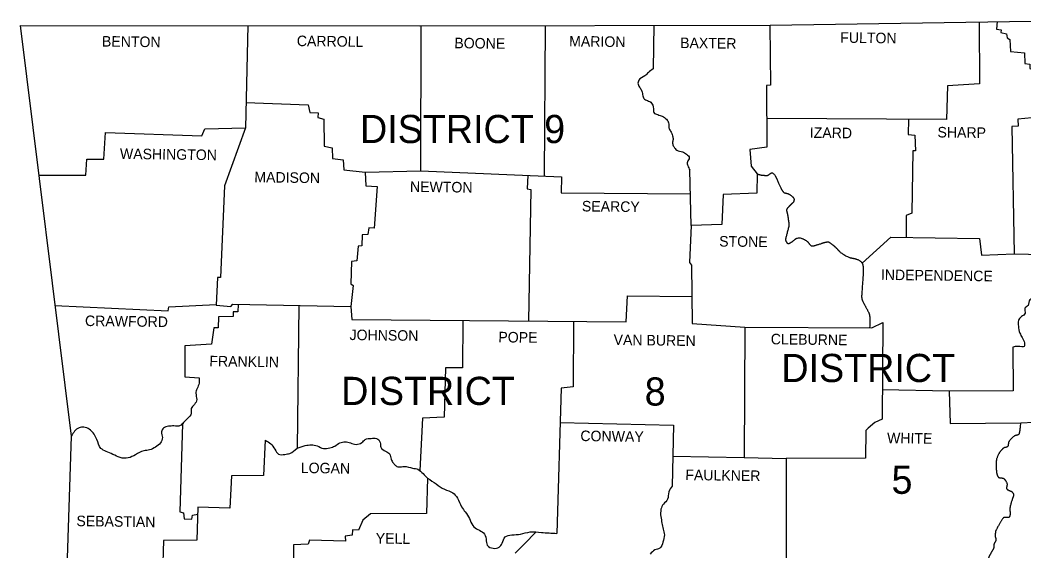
# Model space of a CAD drawing. Extents: x -0.54 to 1.64, y 0 to 0.92.
# Drawn here: x 1.0951 to 1.2805, y 0.7208 to 0.8188 of the extents above; entities that cross this region are included whole.
import ezdxf

# ---------------------------------------------------------------- set-up
doc = ezdxf.new("R2010")
doc.units = 0
doc.layers.add('SHET_Annotations', color=7, linetype='Continuous')

msp = doc.modelspace()

# ---------------------------------------------------------------- linework, layer by layer
at = {"layer": 'SHET_Annotations'}
msp.add_line((1.27998, 0.74446), (1.28519, 0.74474), dxfattribs=at)
for points in [[(1.09511, 0.81784), (1.16886, 0.81779), (1.23365, 0.81792), (1.31002, 0.81909), (1.34545, 0.81992)], [(1.09511, 0.81784), (1.10455, 0.74198), (1.10045, 0.61817)], [(1.1372, 0.81781), (1.13672, 0.79894)], [(1.19208, 0.81784), (1.19192, 0.79004)], [(1.21215, 0.81788), (1.21204, 0.80983)], [(1.23362, 0.81792), (1.23372, 0.80679), (1.23297, 0.80674), (1.23308, 0.79538), (1.22991, 0.79491), (1.23017, 0.79188), (1.23126, 0.79045), (1.23118, 0.78685), (1.22498, 0.78662), (1.22475, 0.78107), (1.2191, 0.78088), (1.21879, 0.77409), (1.21912, 0.77357), (1.21928, 0.76278), (1.229, 0.76213), (1.22887, 0.73809), (1.23665, 0.73789), (1.23665, 0.7134), (1.23053, 0.71294), (1.23009, 0.70759), (1.2198, 0.70752)], [(1.27229, 0.81851), (1.27237, 0.80703), (1.26643, 0.80669), (1.26627, 0.80049), (1.23303, 0.80065)], [(1.27561, 0.81856), (1.27545, 0.81717), (1.27636, 0.81704), (1.27628, 0.81652), (1.27735, 0.81628), (1.27742, 0.81553), (1.27794, 0.81522), (1.27807, 0.81304), (1.28066, 0.81278), (1.28069, 0.81079), (1.28165, 0.81068), (1.28162, 0.8099), (1.28245, 0.80965), (1.28243, 0.807), (1.28313, 0.80687), (1.28331, 0.80091), (1.27945, 0.80054), (1.2795, 0.79927), (1.27833, 0.79919), (1.27872, 0.77567), (1.29711, 0.77526), (1.29742, 0.73864), (1.28541, 0.73833), (1.28519, 0.74474)], [(1.13684, 0.80359), (1.14835, 0.80321), (1.14861, 0.80176), (1.15019, 0.80171), (1.15014, 0.80083), (1.1512, 0.80054), (1.15131, 0.79554), (1.15273, 0.79523), (1.15284, 0.79325), (1.15481, 0.793), (1.15491, 0.79115), (1.15886, 0.79073), (1.16912, 0.791), (1.1692, 0.81779)], [(1.25922, 0.80052), (1.25917, 0.79769), (1.26041, 0.79761), (1.26049, 0.79471), (1.26, 0.79471), (1.25984, 0.78319), (1.25878, 0.78273), (1.25878, 0.77869)], [(1.09854, 0.79022), (1.10724, 0.79019), (1.10745, 0.79318), (1.11059, 0.79318), (1.11087, 0.79805), (1.12869, 0.79743), (1.12921, 0.79878), (1.13672, 0.79894), (1.13289, 0.78825), (1.13214, 0.77131), (1.1316, 0.77129), (1.13134, 0.76618), (1.13401, 0.76595), (1.13442, 0.76636), (1.15618, 0.76595), (1.15641, 0.76353)], [(1.15886, 0.79073), (1.15896, 0.7882), (1.16106, 0.78809), (1.16051, 0.78042), (1.15955, 0.78044), (1.15937, 0.77922), (1.15828, 0.7792), (1.15823, 0.77712), (1.15756, 0.77707), (1.15732, 0.77437), (1.15631, 0.77425), (1.15618, 0.77015), (1.15665, 0.76981), (1.15618, 0.76595)], [(1.16912, 0.791), (1.19511, 0.78991), (1.19508, 0.78693), (1.21895, 0.78677)], [(1.18889, 0.79017), (1.18881, 0.78768), (1.18943, 0.78752), (1.18904, 0.76325)], [(1.2191, 0.78088), (1.21884, 0.79113)], [(1.25066, 0.77392), (1.25595, 0.77873), (1.27237, 0.77847), (1.27268, 0.77544), (1.27872, 0.77567)], [(1.15641, 0.76353), (1.20706, 0.76309), (1.20732, 0.76792), (1.21921, 0.76776)], [(1.10154, 0.76614), (1.12247, 0.76514), (1.12257, 0.76589), (1.13134, 0.76629)], [(1.13538, 0.76634), (1.13533, 0.76493), (1.13447, 0.76493), (1.1345, 0.7641), (1.13175, 0.76405), (1.1317, 0.76203), (1.13092, 0.76203), (1.13048, 0.75897), (1.12555, 0.75871), (1.12553, 0.75295), (1.12817, 0.75275)], [(1.14661, 0.76613), (1.14627, 0.73978)], [(1.1769, 0.76336), (1.17685, 0.75464), (1.17371, 0.75459), (1.17343, 0.74551), (1.16943, 0.74535), (1.16895, 0.73569)], [(1.19737, 0.76318), (1.19729, 0.75109), (1.19506, 0.75088), (1.19423, 0.72404)], [(1.229, 0.76213), (1.25247, 0.76203), (1.25447, 0.76296), (1.25434, 0.74515), (1.25299, 0.74455), (1.25175, 0.74349), (1.25136, 0.74307), (1.25128, 0.73796), (1.23665, 0.73789)], [(1.27849, 0.75843), (1.27856, 0.75039), (1.26674, 0.75033), (1.25438, 0.75057)], [(1.26674, 0.75033), (1.26692, 0.74434), (1.27998, 0.74446)], [(1.12508, 0.74427), (1.12459, 0.728), (1.12532, 0.72782), (1.12542, 0.72673), (1.12682, 0.72666), (1.12693, 0.72741), (1.12793, 0.72757)], [(1.19486, 0.74455), (1.21583, 0.74403), (1.21557, 0.73278)], [(1.27998, 0.74446), (1.27986, 0.74395)], [(1.14041, 0.74123), (1.1401, 0.73472), (1.13416, 0.73467), (1.13383, 0.72873), (1.12796, 0.72889), (1.12778, 0.72279), (1.12161, 0.72271), (1.1214, 0.71659), (1.12532, 0.71639), (1.12516, 0.71449), (1.14558, 0.71393)], [(1.2157, 0.7383), (1.22887, 0.73809)], [(1.17039, 0.73425), (1.17019, 0.72769), (1.15981, 0.72764), (1.15844, 0.72647), (1.15763, 0.72466), (1.15652, 0.72471), (1.15647, 0.7237), (1.15514, 0.72354), (1.1552, 0.72261), (1.14858, 0.72277), (1.14832, 0.72204), (1.1456, 0.72194), (1.14558, 0.71393)], [(1.19037, 0.7243), (1.18831, 0.72209), (1.18655, 0.72041)]]:
    msp.add_lwpolyline(points, dxfattribs=at)
for points in [[(1.21204, 0.80983), (1.21121, 0.80918), (1.21051, 0.80853), (1.2094, 0.80773), (1.20927, 0.807), (1.20963, 0.8063), (1.20999, 0.8057), (1.21015, 0.80487), (1.21046, 0.8042), (1.21121, 0.80389), (1.21189, 0.80332), (1.21209, 0.80251), (1.2122, 0.80174), (1.2129, 0.80137), (1.21373, 0.80106), (1.21453, 0.80052), (1.2149, 0.79987), (1.21495, 0.79896), (1.21528, 0.79831), (1.21565, 0.79746), (1.21573, 0.79678), (1.21565, 0.79611), (1.21586, 0.79546), (1.21643, 0.79481), (1.21746, 0.7945), (1.21822, 0.79406), (1.21873, 0.79341), (1.21837, 0.79266), (1.21845, 0.79196), (1.21884, 0.79113)], [(1.28698, 0.77549), (1.28614, 0.77342), (1.28546, 0.77204), (1.28507, 0.77085), (1.28419, 0.77017), (1.28391, 0.76953), (1.28315, 0.76927), (1.28256, 0.76836), (1.2823, 0.76755), (1.28165, 0.76719), (1.28131, 0.76615), (1.28074, 0.76561), (1.28077, 0.7647), (1.28009, 0.76408), (1.27955, 0.76335), (1.27952, 0.76232), (1.27978, 0.76102), (1.28025, 0.76021), (1.28064, 0.75923), (1.28061, 0.75858), (1.27947, 0.75858), (1.27849, 0.75843)], [(1.12817, 0.75275), (1.12817, 0.75179), (1.12781, 0.7508), (1.12758, 0.74992), (1.12773, 0.74878), (1.12732, 0.74787), (1.12672, 0.74712), (1.12672, 0.74624), (1.12605, 0.74528), (1.12529, 0.74452), (1.12467, 0.74395), (1.1235, 0.74388), (1.12254, 0.74382), (1.12161, 0.74349), (1.12125, 0.74279), (1.1214, 0.74175), (1.12104, 0.74074), (1.12011, 0.73999), (1.11904, 0.73947), (1.11795, 0.73929), (1.11642, 0.73856), (1.11508, 0.73799), (1.1136, 0.73804), (1.11225, 0.73864), (1.111, 0.73918), (1.11004, 0.73975), (1.10929, 0.74141), (1.10877, 0.74235), (1.10789, 0.74328), (1.10688, 0.74364), (1.106, 0.74354), (1.10455, 0.74198)], [(1.14041, 0.74123), (1.1414, 0.74061), (1.14218, 0.73957), (1.14285, 0.73869), (1.14402, 0.73864), (1.14493, 0.73882), (1.14627, 0.73978)], [(1.14627, 0.73978), (1.1478, 0.74027), (1.14889, 0.7404), (1.15001, 0.74019), (1.15115, 0.73973), (1.15234, 0.73986), (1.15325, 0.74017), (1.15418, 0.74076), (1.15517, 0.74095), (1.15615, 0.74076), (1.15717, 0.74048), (1.15823, 0.74082), (1.15888, 0.74139), (1.15997, 0.74159), (1.16095, 0.74159), (1.16163, 0.74082), (1.16176, 0.73996), (1.16264, 0.73921), (1.16339, 0.73869), (1.16365, 0.73776), (1.16404, 0.73706), (1.16445, 0.73659), (1.16505, 0.73633), (1.16606, 0.73641), (1.16762, 0.7361), (1.1686, 0.73589), (1.16954, 0.73508), (1.17039, 0.73425)], [(1.17039, 0.73425), (1.172, 0.73317), (1.1735, 0.73221), (1.17503, 0.73153), (1.17589, 0.73055), (1.17667, 0.72896), (1.17734, 0.728), (1.17812, 0.72681), (1.17874, 0.72551), (1.17968, 0.72476), (1.18069, 0.72414), (1.18118, 0.723), (1.18141, 0.72186), (1.18253, 0.72129), (1.18359, 0.72152), (1.18416, 0.72222), (1.18473, 0.72339), (1.18595, 0.72378), (1.18754, 0.72391), (1.18935, 0.72432), (1.1914, 0.72424), (1.19423, 0.72404)], [(1.21557, 0.73278), (1.21495, 0.73171), (1.21471, 0.73034), (1.21396, 0.72946), (1.2135, 0.7285), (1.21347, 0.72715), (1.21368, 0.72596), (1.21391, 0.72484), (1.21412, 0.72378), (1.21386, 0.72245), (1.21326, 0.72131), (1.21238, 0.72098), (1.2115, 0.7202)]]:
    msp.add_spline(points, degree=3, dxfattribs=at)
for points in [[(1.23126, 0.79045), (1.2314, 0.79038), (1.23155, 0.79033), (1.23171, 0.79029), (1.23186, 0.79025), (1.23201, 0.79022), (1.23216, 0.7902), (1.23232, 0.79018), (1.23247, 0.79017), (1.23262, 0.79016), (1.23277, 0.79015), (1.23292, 0.79014), (1.23308, 0.79014), (1.23318, 0.79014), (1.23328, 0.79019), (1.23337, 0.79024), (1.23347, 0.7903), (1.23355, 0.79038), (1.23365, 0.79045), (1.23374, 0.79051), (1.23383, 0.79056), (1.23393, 0.79061), (1.23397, 0.79063), (1.23402, 0.79063), (1.23406, 0.79062), (1.23411, 0.79061), (1.23415, 0.79059), (1.23419, 0.79056), (1.23439, 0.79038), (1.23454, 0.79021), (1.23466, 0.78999), (1.23471, 0.78988), (1.23477, 0.78978), (1.23482, 0.78967), (1.23487, 0.78956), (1.23492, 0.78945), (1.23497, 0.78934), (1.2351, 0.78904), (1.23523, 0.78873), (1.23536, 0.78843), (1.23546, 0.78821), (1.23556, 0.78798), (1.23567, 0.78776), (1.23572, 0.78765), (1.23578, 0.78755), (1.23585, 0.78744), (1.23588, 0.78739), (1.23591, 0.78734), (1.23595, 0.78729), (1.23598, 0.78723), (1.23602, 0.78718), (1.23606, 0.78713), (1.23612, 0.78706), (1.23619, 0.787), (1.23628, 0.78696), (1.23638, 0.78692), (1.23647, 0.7869), (1.23657, 0.78687), (1.23667, 0.78685), (1.23677, 0.78683), (1.23687, 0.78681), (1.23692, 0.78679), (1.23697, 0.78678), (1.23701, 0.78676), (1.23706, 0.78674), (1.2371, 0.78672), (1.23715, 0.78669), (1.23731, 0.7866), (1.23745, 0.7865), (1.2376, 0.78638), (1.23767, 0.78632), (1.23773, 0.78626), (1.2378, 0.7862), (1.23786, 0.78614), (1.23792, 0.78607), (1.23798, 0.78599), (1.23802, 0.78594), (1.23804, 0.78588), (1.23806, 0.78581), (1.23808, 0.78574), (1.23809, 0.78567), (1.23808, 0.7856), (1.23807, 0.7855), (1.23805, 0.7854), (1.238, 0.7853), (1.23799, 0.78527), (1.23797, 0.78524), (1.23795, 0.78522), (1.2379, 0.78515), (1.23784, 0.78508), (1.23778, 0.78503), (1.23772, 0.78497), (1.23766, 0.78491), (1.23759, 0.78485), (1.23753, 0.78479), (1.23746, 0.78474), (1.2374, 0.78468), (1.23734, 0.78462), (1.23728, 0.78455), (1.23723, 0.78449), (1.2372, 0.78446), (1.23717, 0.78443), (1.23715, 0.7844), (1.23707, 0.78431), (1.23698, 0.78423), (1.23689, 0.78413), (1.23684, 0.78408), (1.2368, 0.78401), (1.23676, 0.78395), (1.23674, 0.78391), (1.23673, 0.78388), (1.23672, 0.78384), (1.23671, 0.78381), (1.23671, 0.78377), (1.23671, 0.78374), (1.23671, 0.78366), (1.23671, 0.78359), (1.23673, 0.78352), (1.23674, 0.78344), (1.23676, 0.78337), (1.23678, 0.7833), (1.2368, 0.78322), (1.23682, 0.78315), (1.23684, 0.78308), (1.23686, 0.783), (1.23687, 0.78293), (1.23689, 0.78286), (1.23692, 0.78266), (1.23695, 0.78246), (1.23698, 0.78226), (1.23701, 0.78206), (1.23704, 0.78186), (1.23707, 0.78166), (1.23712, 0.78129), (1.23716, 0.78091), (1.23707, 0.78055), (1.23698, 0.78019), (1.23688, 0.77984), (1.23678, 0.77948), (1.2367, 0.77917), (1.23663, 0.77887), (1.23655, 0.77855), (1.23653, 0.77848), (1.23653, 0.77841), (1.23653, 0.77834), (1.23652, 0.77826), (1.23653, 0.77819), (1.23655, 0.77812), (1.23657, 0.77804), (1.2366, 0.77797), (1.23664, 0.77791), (1.23666, 0.77787), (1.23668, 0.77783), (1.2367, 0.7778), (1.23673, 0.77776), (1.23676, 0.77773), (1.23678, 0.77769), (1.23681, 0.77766), (1.23684, 0.77764), (1.23688, 0.77762), (1.23691, 0.7776), (1.23695, 0.77759), (1.23698, 0.77758), (1.23706, 0.77758), (1.23714, 0.77759), (1.23721, 0.77762), (1.23736, 0.77769), (1.2375, 0.77777), (1.23764, 0.77785), (1.23768, 0.77787), (1.23772, 0.7779), (1.23776, 0.77792), (1.2378, 0.77795), (1.23784, 0.77798), (1.23787, 0.77801), (1.23795, 0.77807), (1.23802, 0.77814), (1.2381, 0.77821), (1.23817, 0.77827), (1.23825, 0.77833), (1.23832, 0.77839), (1.2384, 0.77845), (1.23848, 0.77849), (1.23857, 0.77852), (1.23888, 0.77863), (1.23923, 0.77864), (1.23953, 0.77852), (1.23969, 0.77846), (1.23985, 0.77839), (1.24, 0.7783), (1.24015, 0.77822), (1.2403, 0.77814), (1.24044, 0.77803), (1.24053, 0.77796), (1.24061, 0.77789), (1.24068, 0.7778), (1.24075, 0.77771), (1.24082, 0.77761), (1.24089, 0.77752), (1.24096, 0.77744), (1.24103, 0.77736), (1.24111, 0.77728), (1.24115, 0.77724), (1.24119, 0.77722), (1.24123, 0.77719), (1.24126, 0.77718), (1.24128, 0.77717), (1.2413, 0.77717), (1.24133, 0.77716), (1.24135, 0.77715), (1.24137, 0.77715), (1.24153, 0.77713), (1.2417, 0.77714), (1.24185, 0.77719), (1.24201, 0.77723), (1.24217, 0.77728), (1.24233, 0.77733), (1.2426, 0.77742), (1.24287, 0.7775), (1.24314, 0.77759), (1.24332, 0.77765), (1.2435, 0.77771), (1.24368, 0.77776), (1.24377, 0.77779), (1.24386, 0.77781), (1.24396, 0.77783), (1.244, 0.77784), (1.24405, 0.77785), (1.24409, 0.77786), (1.24414, 0.77787), (1.24418, 0.77787), (1.24423, 0.77788), (1.24437, 0.77788), (1.24451, 0.77784), (1.24463, 0.77776), (1.24476, 0.77767), (1.24488, 0.77758), (1.24501, 0.77749), (1.24512, 0.7774), (1.24524, 0.77731), (1.24535, 0.77722), (1.24547, 0.77713), (1.24558, 0.77704), (1.24568, 0.77694), (1.24575, 0.77687), (1.24582, 0.7768), (1.24589, 0.77673), (1.24596, 0.77666), (1.24603, 0.77659), (1.24609, 0.77651), (1.24616, 0.77644), (1.24623, 0.77637), (1.2463, 0.77629), (1.24636, 0.77622), (1.24644, 0.77615), (1.24651, 0.77609), (1.24675, 0.77587), (1.24701, 0.77569), (1.24729, 0.77552), (1.2476, 0.77532), (1.24793, 0.77516), (1.24827, 0.77502), (1.24837, 0.77498), (1.24847, 0.77495), (1.24858, 0.77493), (1.24868, 0.7749), (1.24879, 0.77488), (1.24889, 0.77486), (1.249, 0.77484), (1.2491, 0.77482), (1.24921, 0.7748), (1.24931, 0.77478), (1.24941, 0.77475), (1.24952, 0.77471), (1.24974, 0.77464), (1.24996, 0.77455), (1.25017, 0.77443), (1.25027, 0.77438), (1.25036, 0.77431), (1.25045, 0.77422), (1.25049, 0.77418), (1.25053, 0.77414), (1.25056, 0.77409), (1.25058, 0.77407), (1.2506, 0.77404), (1.25061, 0.77402), (1.25063, 0.77399), (1.25064, 0.77396), (1.25066, 0.77393), (1.25069, 0.77388), (1.25071, 0.77383), (1.25073, 0.77377), (1.25079, 0.77361), (1.25082, 0.77344), (1.25083, 0.77328), (1.25084, 0.77317), (1.25085, 0.77306), (1.25085, 0.77294), (1.25084, 0.77283), (1.25084, 0.77272), (1.25084, 0.77261), (1.25084, 0.77242), (1.25084, 0.77223), (1.25084, 0.77204), (1.25083, 0.77185), (1.25083, 0.77166), (1.25081, 0.77147), (1.25078, 0.77099), (1.25074, 0.77052), (1.25071, 0.77004), (1.25068, 0.76953), (1.25064, 0.76902), (1.25061, 0.76851), (1.2506, 0.76838), (1.25059, 0.76826), (1.25058, 0.76813), (1.25057, 0.768), (1.25057, 0.76787), (1.25057, 0.76774), (1.25057, 0.76761), (1.25059, 0.76748), (1.25061, 0.76736), (1.25064, 0.76723), (1.25068, 0.7671), (1.25074, 0.76698), (1.25082, 0.76681), (1.25091, 0.76665), (1.251, 0.76648), (1.25108, 0.76632), (1.25117, 0.76616), (1.25126, 0.766), (1.25136, 0.7658), (1.25146, 0.7656), (1.25157, 0.7654), (1.25167, 0.7652), (1.25178, 0.76501), (1.25188, 0.76481), (1.25196, 0.76464), (1.25201, 0.76445), (1.25204, 0.76426), (1.25205, 0.76417), (1.25206, 0.76407), (1.25207, 0.76398), (1.25207, 0.76388), (1.25208, 0.76379), (1.25209, 0.76369), (1.2521, 0.76341), (1.25211, 0.76314), (1.25211, 0.76286), (1.25211, 0.76258), (1.25208, 0.76231), (1.25204, 0.76203)], [(1.27986, 0.74395), (1.27985, 0.74383), (1.27984, 0.7437), (1.27983, 0.74357), (1.27982, 0.74344), (1.27981, 0.74331), (1.2798, 0.74318), (1.27978, 0.74306), (1.27976, 0.74293), (1.27973, 0.7428), (1.27972, 0.74274), (1.2797, 0.74268), (1.27969, 0.74261), (1.27968, 0.74258), (1.27967, 0.74255), (1.27966, 0.74252), (1.27965, 0.74249), (1.27964, 0.74246), (1.27963, 0.74242), (1.2796, 0.74235), (1.27955, 0.74229), (1.27948, 0.74225), (1.2794, 0.74222), (1.27932, 0.74219), (1.27924, 0.74217), (1.27915, 0.74215), (1.27906, 0.74214), (1.27897, 0.74212), (1.27893, 0.7421), (1.27889, 0.74209), (1.27885, 0.74207), (1.27881, 0.74206), (1.27878, 0.74203), (1.27875, 0.74201), (1.27856, 0.74187), (1.2784, 0.74171), (1.27824, 0.74155), (1.27807, 0.74138), (1.27792, 0.74122), (1.27779, 0.74102), (1.27774, 0.74096), (1.27771, 0.74088), (1.27769, 0.7408), (1.27768, 0.74072), (1.27768, 0.74063), (1.27766, 0.74055), (1.27765, 0.74047), (1.27764, 0.74038), (1.27763, 0.7403), (1.27762, 0.74022), (1.27758, 0.74015), (1.27753, 0.74009), (1.27748, 0.74003), (1.27742, 0.73999), (1.27735, 0.73997), (1.27728, 0.73995), (1.2772, 0.73993), (1.27713, 0.73992), (1.27706, 0.7399), (1.27698, 0.73988), (1.27691, 0.73986), (1.27684, 0.73984), (1.27678, 0.7398), (1.27672, 0.73975), (1.27664, 0.73968), (1.27657, 0.73961), (1.2765, 0.73953), (1.27642, 0.73945), (1.27635, 0.73938), (1.27628, 0.7393), (1.27621, 0.73922), (1.27615, 0.73913), (1.27609, 0.73905), (1.27603, 0.73896), (1.27597, 0.73886), (1.27592, 0.73877), (1.2758, 0.73856), (1.27571, 0.73834), (1.27563, 0.73812), (1.27554, 0.7379), (1.27547, 0.73768), (1.27545, 0.73744), (1.27541, 0.737), (1.27541, 0.73654), (1.27543, 0.7361), (1.27543, 0.73596), (1.27544, 0.73583), (1.27545, 0.7357), (1.27546, 0.73557), (1.27548, 0.73544), (1.2755, 0.73531), (1.27552, 0.73518), (1.27555, 0.73505), (1.27559, 0.73492), (1.27561, 0.73486), (1.27563, 0.73479), (1.27566, 0.73473), (1.27568, 0.73467), (1.2757, 0.7346), (1.27574, 0.73454), (1.27578, 0.73445), (1.27586, 0.73438), (1.27595, 0.73435), (1.27606, 0.73433), (1.27616, 0.73432), (1.27627, 0.7343), (1.27638, 0.73429), (1.27649, 0.73428), (1.27661, 0.73426), (1.27671, 0.73425), (1.2768, 0.7342), (1.27688, 0.73413), (1.27691, 0.73409), (1.27694, 0.73406), (1.27697, 0.73403), (1.277, 0.73399), (1.27702, 0.73396), (1.27705, 0.73392), (1.2771, 0.73385), (1.27715, 0.73378), (1.2772, 0.73371), (1.27729, 0.73356), (1.27737, 0.73341), (1.27742, 0.73324), (1.27745, 0.73317), (1.27746, 0.73308), (1.27744, 0.73301), (1.27742, 0.73292), (1.2774, 0.73284), (1.27739, 0.73276), (1.27737, 0.73267), (1.27735, 0.73259), (1.27734, 0.73251), (1.27732, 0.73243), (1.27734, 0.73236), (1.27737, 0.73228), (1.27739, 0.73224), (1.27742, 0.7322), (1.27746, 0.73217), (1.2775, 0.73213), (1.27754, 0.7321), (1.27758, 0.73208), (1.27768, 0.73204), (1.27778, 0.73199), (1.27788, 0.73195), (1.27798, 0.73191), (1.27809, 0.73187), (1.27819, 0.73183), (1.27829, 0.73178), (1.27837, 0.7317), (1.27843, 0.73161), (1.27846, 0.73157), (1.27849, 0.73152), (1.27852, 0.73148), (1.27855, 0.73144), (1.27857, 0.7314), (1.2786, 0.73135), (1.27862, 0.73131), (1.27863, 0.73127), (1.27864, 0.73122), (1.27865, 0.73118), (1.27865, 0.73113), (1.27864, 0.73109), (1.27863, 0.73104), (1.27861, 0.73099), (1.2786, 0.73094), (1.27858, 0.73089), (1.27856, 0.73084), (1.27854, 0.73079), (1.27852, 0.73074), (1.2785, 0.73069), (1.27848, 0.73064), (1.27847, 0.73059), (1.27845, 0.73054), (1.27843, 0.73049), (1.27835, 0.73022), (1.27826, 0.72994), (1.27818, 0.72966), (1.2781, 0.72938), (1.27803, 0.7291), (1.27797, 0.72881), (1.27795, 0.72871), (1.27794, 0.72862), (1.27794, 0.72853), (1.27794, 0.72843), (1.27795, 0.72834), (1.27796, 0.72824), (1.27797, 0.72814), (1.27798, 0.72805), (1.27798, 0.72795), (1.27799, 0.72786), (1.27799, 0.72776), (1.27799, 0.72767), (1.27799, 0.72758), (1.27798, 0.72749), (1.27797, 0.72741), (1.27796, 0.72736), (1.27795, 0.72732), (1.27794, 0.72728), (1.27793, 0.72723), (1.27791, 0.72719), (1.27789, 0.72715), (1.27784, 0.72706), (1.27775, 0.72699), (1.27765, 0.72698), (1.27753, 0.72697), (1.27741, 0.72698), (1.27729, 0.72698), (1.27717, 0.72698), (1.27705, 0.72698), (1.27693, 0.72698), (1.27683, 0.72698), (1.27673, 0.72692), (1.27667, 0.72684), (1.27654, 0.72663), (1.27642, 0.72643), (1.27629, 0.72622), (1.27617, 0.72601), (1.27604, 0.7258), (1.27592, 0.72559), (1.27575, 0.72531), (1.27559, 0.72502), (1.27543, 0.72474), (1.2754, 0.72469), (1.27538, 0.72464), (1.27536, 0.72459), (1.27532, 0.72445), (1.27528, 0.7243), (1.27527, 0.72416), (1.27526, 0.72406), (1.27526, 0.72396), (1.27525, 0.72386), (1.27525, 0.72376), (1.27525, 0.72367), (1.27524, 0.72357), (1.27524, 0.7235), (1.27525, 0.72344), (1.27527, 0.72338), (1.27528, 0.72331), (1.2753, 0.72325), (1.27532, 0.72318), (1.27534, 0.72312), (1.27535, 0.72305), (1.27537, 0.72299), (1.27538, 0.72292), (1.27538, 0.72286), (1.27537, 0.72279), (1.27536, 0.72273), (1.27535, 0.72267), (1.27531, 0.72262), (1.27528, 0.72256), (1.27525, 0.7225), (1.27522, 0.72245), (1.27518, 0.7224), (1.27515, 0.72234), (1.27511, 0.72229), (1.27508, 0.72223), (1.27505, 0.72218), (1.27504, 0.72212), (1.27502, 0.72204), (1.275, 0.72196), (1.275, 0.72188), (1.27499, 0.7218), (1.27499, 0.72172), (1.27498, 0.72163), (1.27498, 0.72155), (1.27497, 0.72147), (1.27496, 0.72139), (1.27494, 0.72131), (1.27492, 0.72123), (1.27488, 0.72116), (1.27485, 0.72109), (1.27481, 0.72102), (1.27477, 0.72095), (1.27473, 0.72089), (1.27469, 0.72082), (1.27465, 0.72076), (1.27457, 0.72062), (1.27449, 0.72049), (1.27441, 0.72035), (1.27434, 0.72023), (1.27428, 0.7201), (1.27421, 0.71997), (1.27414, 0.71984), (1.27408, 0.71971), (1.27403, 0.71958), (1.274, 0.71951), (1.274, 0.71941), (1.27405, 0.71935), (1.2741, 0.71927), (1.27416, 0.71919), (1.27422, 0.71911), (1.27428, 0.71904), (1.27434, 0.71897), (1.2744, 0.71888), (1.27445, 0.71881), (1.27448, 0.71872), (1.27447, 0.71864), (1.27445, 0.71854), (1.27443, 0.71844), (1.27441, 0.71833), (1.27438, 0.71823), (1.27436, 0.71812), (1.27434, 0.71802), (1.27426, 0.71769), (1.27412, 0.71737), (1.27408, 0.71703)]]:
    msp.add_open_spline(points, degree=3, dxfattribs=at)

# ---------------------------------------------------------------- texts
for s, height, rotation, p in [('CARROLL', 0.001945, 359.267, (1.14622, 0.81403)), ('FULTON', 0.001945, 359.282, (1.24661, 0.81465)), ('BENTON', 0.001945, 359.2874, (1.11022, 0.81395)), ('BOONE', 0.001945, 359.3139, (1.17532, 0.81364)), ('MARION', 0.001945, 359.2237, (1.19653, 0.81398)), ('BAXTER', 0.001945, 359.2892, (1.21703, 0.81367)), ('IZARD', 0.001945, 359.1987, (1.24098, 0.7971)), ('SHARP', 0.001945, 359.3013, (1.26457, 0.79717)), ('WASHINGTON', 0.001945, 359.2079, (1.11354, 0.7932)), ('MADISON', 0.001945, 359.217, (1.13837, 0.78888)), ('NEWTON', 0.001945, 359.303, (1.16712, 0.78711)), ('SEARCY', 0.001945, 359.2838, (1.19888, 0.78351)), ('STONE', 0.001945, 359.3139, (1.22424, 0.77702)), ('INDEPENDENCE', 0.0019451, 359.254, (1.25412, 0.77085)), ('CRAWFORD', 0.001945, 359.2748, (1.10709, 0.76234)), ('JOHNSON', 0.001945, 359.2575, (1.15596, 0.75975)), ('POPE', 0.001945, 359.3389, (1.18345, 0.75933)), ('VAN BUREN', 0.001945, 359.2547, (1.20474, 0.75884)), ('CLEBURNE', 0.001945, 359.2518, (1.23377, 0.75897)), ('FRANKLIN', 0.001945, 359.1782, (1.13006, 0.7549)), ('CONWAY', 0.001945, 359.1737, (1.1986, 0.7411)), ('WHITE', 0.001945, 359.2125, (1.25525, 0.74071)), ('LOGAN', 0.001945, 359.3076, (1.14696, 0.73519)), ('FAULKNER', 0.001945, 359.2447, (1.21799, 0.73389)), ('SEBASTIAN', 0.001945, 359.1959, (1.1055, 0.72539)), ('YELL', 0.001945, 359.3097, (1.1608, 0.72217))]:
    msp.add_text(s, height=height, rotation=rotation, dxfattribs=at).set_placement(p)
for s, height, p in [('DISTRICT 9', 0.005203, (1.15791, 0.79612)), ('DISTRICT', 0.005203, (1.23574, 0.75199)), ('DISTRICT', 0.005203, (1.15443, 0.74776)), ('8', 0.0052, (1.21049, 0.74765)), ('5', 0.0052, (1.25609, 0.73135))]:
    msp.add_text(s, height=height, dxfattribs=at).set_placement(p)

doc.saveas('drawing.dxf')
